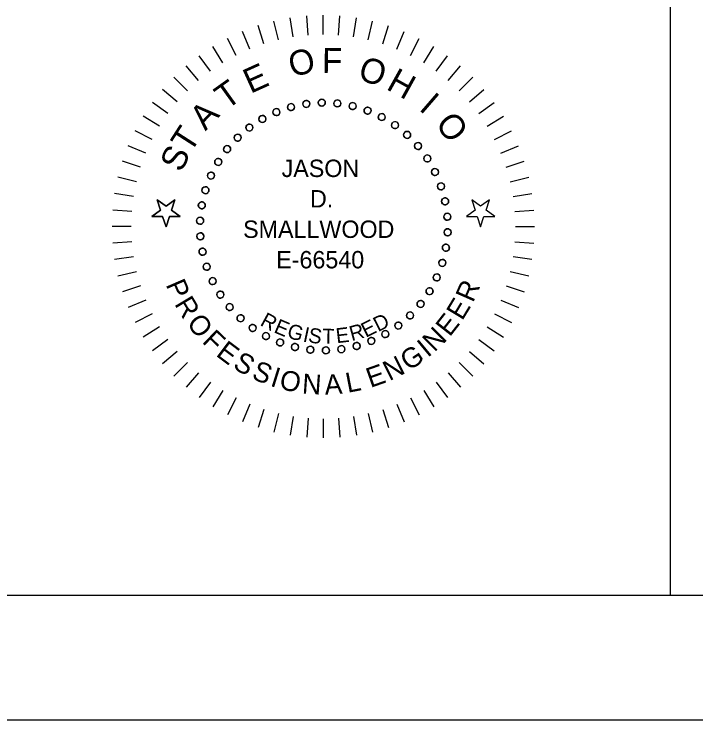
# Model space of a CAD drawing. Extents: x -5.9 to 34, y 0 to 22.
# Drawn here: x 26.559 to 29.302, y 0 to 2.839 of the extents above; entities that cross this region are included whole.
import ezdxf

# ---------------------------------------------------------------- set-up
doc = ezdxf.new("R2010")
doc.units = 0
for name, color, linetype in [('Default', 7, 'Continuous'), ('SH_Border', 7, 'Continuous'), ('SH_Cut_Line', 7, 'Continuous'), ('SH_Data', 7, 'Continuous')]:
    doc.layers.add(name, color=color, linetype=linetype)

msp = doc.modelspace()

# ---------------------------------------------------------------- linework, layer by layer
at = {"layer": 'Default'}
for points in [[(27.6225, 2.7359), (27.6045, 2.8109)], [(27.6821, 2.7478), (27.67, 2.8239)], [(27.7423, 2.7549), (27.7363, 2.8317)], [(27.803, 2.7573), (27.803, 2.8343)], [(27.8636, 2.7549), (27.8697, 2.8317)], [(27.9239, 2.7478), (27.936, 2.8239)], [(27.9834, 2.7359), (28.0014, 2.8109)], [(27.5641, 2.7195), (27.5403, 2.7927)], [(28.0418, 2.7195), (28.0657, 2.7927)], [(27.5072, 2.6984), (27.4777, 2.7696)], [(28.0988, 2.6984), (28.1283, 2.7696)], [(27.4521, 2.673), (27.4171, 2.7417)], [(28.1539, 2.673), (28.1889, 2.7417)], [(27.3991, 2.6434), (27.3588, 2.7091)], [(28.2069, 2.6434), (28.2471, 2.7091)], [(27.3487, 2.6097), (27.3034, 2.672)], [(28.2573, 2.6097), (28.3026, 2.672)], [(27.301, 2.5721), (27.2509, 2.6307)], [(28.305, 2.5721), (28.355, 2.6307)], [(27.2564, 2.5309), (27.2019, 2.5854)], [(28.3495, 2.5309), (28.404, 2.5854)], [(27.2152, 2.4863), (27.1566, 2.5364)], [(28.3907, 2.4863), (28.4493, 2.5364)], [(27.1776, 2.4387), (27.1153, 2.484)], [(28.4283, 2.4387), (28.4907, 2.484)], [(27.1439, 2.3882), (27.0782, 2.4285)], [(28.462, 2.3882), (28.5277, 2.4285)], [(27.1143, 2.3352), (27.0456, 2.3702)], [(28.4917, 2.3352), (28.5604, 2.3702)], [(27.0889, 2.2801), (27.0177, 2.3096)], [(28.5171, 2.2801), (28.5883, 2.3096)], [(27.0679, 2.2232), (26.9946, 2.247)], [(28.5381, 2.2232), (28.6114, 2.247)], [(27.0514, 2.1648), (26.9764, 2.1828)], [(28.5546, 2.1648), (28.6295, 2.1828)], [(27.0395, 2.1052), (26.9634, 2.1173)], [(28.5664, 2.1052), (28.6425, 2.1173)], [(27.1484, 2.0511), (27.1131, 2.0254), (27.1567, 2.0254), (27.1702, 1.984), (27.1837, 2.0254), (27.2273, 2.0254), (27.192, 2.0511), (27.2055, 2.0925), (27.1702, 2.0669), (27.1349, 2.0925), (27.1484, 2.0511)], [(28.471, 2.0925), (28.4358, 2.0669), (28.4005, 2.0925), (28.414, 2.0511), (28.3787, 2.0254), (28.4223, 2.0254), (28.4358, 1.984), (28.4492, 2.0254), (28.4928, 2.0254), (28.4576, 2.0511), (28.471, 2.0925)], [(27.0324, 2.045), (26.9556, 2.051)], [(28.5736, 2.045), (28.6504, 2.051)], [(27.03, 1.9843), (26.953, 1.9843)], [(28.5759, 1.9843), (28.653, 1.9843)], [(27.0324, 1.9237), (26.9556, 1.9176)], [(28.5736, 1.9237), (28.6504, 1.9176)], [(27.0395, 1.8634), (26.9634, 1.8514)], [(28.6425, 1.8514), (28.5664, 1.8634)], [(26.9764, 1.7859), (27.0514, 1.8039)], [(28.5546, 1.8039), (28.6295, 1.7859)], [(27.0679, 1.7455), (26.9946, 1.7217)], [(28.5381, 1.7455), (28.6114, 1.7217)], [(27.0889, 1.6885), (27.0177, 1.659)], [(28.5171, 1.6885), (28.5883, 1.659)], [(27.1143, 1.6334), (27.0456, 1.5984)], [(28.4917, 1.6334), (28.5604, 1.5984)], [(27.1439, 1.5805), (27.0782, 1.5402)], [(28.462, 1.5805), (28.5277, 1.5402)], [(27.1776, 1.53), (27.1153, 1.4847)], [(28.4283, 1.53), (28.4907, 1.4847)], [(27.2152, 1.4823), (27.1566, 1.4323)], [(28.3907, 1.4823), (28.4493, 1.4323)], [(27.2564, 1.4378), (27.2019, 1.3833)], [(28.3495, 1.4378), (28.404, 1.3833)], [(27.301, 1.3966), (27.2509, 1.338)], [(28.305, 1.3966), (28.355, 1.338)], [(27.3487, 1.359), (27.3034, 1.2966)], [(28.2573, 1.359), (28.3026, 1.2966)], [(27.3991, 1.3253), (27.3588, 1.2596)], [(28.2069, 1.3253), (28.2471, 1.2596)], [(27.4521, 1.2956), (27.4171, 1.227)], [(28.1539, 1.2956), (28.1889, 1.227)], [(27.5072, 1.2702), (27.4777, 1.199)], [(28.0988, 1.2702), (28.1283, 1.199)], [(27.5641, 1.2492), (27.5403, 1.1759)], [(27.6225, 1.2327), (27.6045, 1.1578)], [(27.6821, 1.2209), (27.67, 1.1448)], [(27.9239, 1.2209), (27.936, 1.1448)], [(27.9834, 1.2327), (28.0014, 1.1578)], [(28.0418, 1.2492), (28.0657, 1.1759)], [(27.7423, 1.2138), (27.7363, 1.1369)], [(27.803, 1.2114), (27.803, 1.1343)], [(27.8636, 1.2138), (27.8697, 1.1369)]]:
    msp.add_lwpolyline(points, dxfattribs=at)
for points in [[(27.1349, 2.0925), (27.1702, 2.0669), (27.2055, 2.0925), (27.192, 2.0511), (27.2273, 2.0254), (27.1837, 2.0254), (27.1702, 1.984), (27.1567, 2.0254), (27.1131, 2.0254), (27.1484, 2.0511)], [(28.471, 2.0925), (28.4358, 2.0669), (28.4005, 2.0925), (28.414, 2.0511), (28.3787, 2.0254), (28.4223, 2.0254), (28.4358, 1.984), (28.4492, 2.0254), (28.4928, 2.0254), (28.4576, 2.0511)]]:
    msp.add_lwpolyline(points, close=True, dxfattribs=at)
for centre in [(27.6734, 2.4652), (27.7347, 2.4779), (27.797, 2.4829), (27.8596, 2.48), (27.9212, 2.4692), (27.6142, 2.4449), (27.981, 2.4509), (27.558, 2.4173), (28.0381, 2.4251), (27.5057, 2.3829), (28.0915, 2.3925), (28.1403, 2.3534), (27.4582, 2.3423), (27.4161, 2.296), (28.1839, 2.3085), (28.2215, 2.2584), (27.3801, 2.2447), (28.2525, 2.2041), (27.3509, 2.1894), (28.2765, 2.1463), (27.3288, 2.1309), (27.3142, 2.07), (28.2931, 2.0859), (27.3074, 2.0078), (28.3019, 2.024), (27.3084, 1.9452), (28.3029, 1.9614), (28.2961, 1.8992), (27.3172, 1.8833), (28.2815, 1.8383), (27.3338, 1.8229), (28.2594, 1.7798), (27.3578, 1.7651), (28.2302, 1.7245), (27.3888, 1.7108), (28.1942, 1.6732), (27.4264, 1.6607), (27.47, 1.6158), (28.1521, 1.6269), (27.5188, 1.5767), (28.1046, 1.5863), (28.0523, 1.5519), (27.5722, 1.5441), (27.9961, 1.5243), (27.6293, 1.5183), (27.6891, 1.5), (27.8756, 1.4913), (27.9369, 1.504), (27.7507, 1.4892), (27.8133, 1.4863)]:
    msp.add_circle(centre, 0.0141, dxfattribs=at)
for centre, radius, start, end in [((27.6734, 2.4652), 0.0141, 14.4, 194.4), ((27.7347, 2.4779), 0.0141, 7.2, 187.2), ((27.7347, 2.4779), 0.0141, 187.2, 270.9371), ((27.7347, 2.4779), 0.0141, 285.3271, 7.2), ((27.797, 2.4829), 0.0141, 0, 180), ((27.797, 2.4829), 0.0141, 180, 263.7371), ((27.797, 2.4829), 0.0141, 278.1271, 360), ((27.8596, 2.48), 0.0141, 172.8, 256.5371), ((27.8596, 2.48), 0.0141, 352.8, 172.8), ((27.8596, 2.48), 0.0141, 270.9271, 352.8), ((27.9212, 2.4692), 0.0141, 165.6, 249.3371), ((27.9212, 2.4692), 0.0141, 345.6, 165.6), ((27.6142, 2.4449), 0.0141, 21.6, 201.6), ((27.6142, 2.4449), 0.0141, 299.7271, 21.6), ((27.6734, 2.4652), 0.0141, 194.4, 278.1371), ((27.8052, 1.9846), 0.4843, 105.1226, 105.5416), ((27.6734, 2.4652), 0.0141, 292.5271, 14.4), ((27.8052, 1.9846), 0.4843, 97.9226, 98.3416), ((27.8052, 1.9846), 0.4843, 90.7226, 91.1416), ((27.8052, 1.9846), 0.4843, 83.5226, 83.9416), ((27.8052, 1.9846), 0.4843, 76.3226, 76.7416), ((27.9212, 2.4692), 0.0141, 263.7271, 345.6), ((27.981, 2.4509), 0.0141, 158.4, 242.1371), ((27.981, 2.4509), 0.0141, 338.4, 158.4), ((27.981, 2.4509), 0.0141, 256.5271, 338.4), ((27.558, 2.4173), 0.0141, 28.8, 208.8), ((27.558, 2.4173), 0.0141, 306.9271, 28.8), ((27.6142, 2.4449), 0.0141, 201.6, 285.3371), ((27.8052, 1.9846), 0.4843, 112.3226, 112.7416), ((27.8052, 1.9846), 0.4843, 69.1226, 69.5416), ((28.0381, 2.4251), 0.0141, 151.2, 234.9371), ((28.0381, 2.4251), 0.0141, 331.2, 151.2), ((27.8052, 1.9846), 0.4843, 61.9226, 62.3416), ((28.0381, 2.4251), 0.0141, 249.3271, 331.2), ((27.5057, 2.3829), 0.0141, 36, 216), ((27.5057, 2.3829), 0.0141, 314.1271, 36), ((27.558, 2.4173), 0.0141, 208.8, 292.5371), ((27.8052, 1.9846), 0.4843, 119.5226, 119.9416), ((28.0915, 2.3925), 0.0141, 144, 227.7371), ((28.0915, 2.3925), 0.0141, 324, 144), ((27.5057, 2.3829), 0.0141, 216, 299.7371), ((27.8052, 1.9846), 0.4843, 126.7226, 127.1416), ((27.8052, 1.9846), 0.4843, 54.7226, 55.1416), ((28.0915, 2.3925), 0.0141, 242.1271, 324), ((28.1403, 2.3534), 0.0141, 136.8, 220.5371), ((28.1403, 2.3534), 0.0141, 316.8, 136.8), ((27.4582, 2.3423), 0.0141, 43.2, 223.2), ((27.4582, 2.3423), 0.0141, 223.2, 306.9371), ((27.8052, 1.9846), 0.4843, 133.9226, 134.3416), ((27.4582, 2.3423), 0.0141, 321.3271, 43.2), ((27.8052, 1.9846), 0.4843, 47.5226, 47.9416), ((28.1403, 2.3534), 0.0141, 234.9271, 316.8), ((27.4161, 2.296), 0.0141, 50.4, 230.4), ((27.4161, 2.296), 0.0141, 328.5271, 50.4), ((28.1839, 2.3085), 0.0141, 129.6, 213.3371), ((27.8052, 1.9846), 0.4843, 40.3226, 40.7416), ((28.1839, 2.3085), 0.0141, 309.6, 129.6), ((27.4161, 2.296), 0.0141, 230.4, 314.1371), ((27.8052, 1.9846), 0.4843, 141.1226, 141.5416), ((28.1839, 2.3085), 0.0141, 227.7271, 309.6), ((28.2215, 2.2584), 0.0141, 302.4, 122.4), ((27.3801, 2.2447), 0.0141, 57.6, 237.6), ((27.3801, 2.2447), 0.0141, 335.7271, 57.6), ((28.2215, 2.2584), 0.0141, 122.4, 206.1371), ((27.8052, 1.9846), 0.4843, 33.1226, 33.5416), ((28.2215, 2.2584), 0.0141, 220.5271, 302.4), ((27.3801, 2.2447), 0.0141, 237.6, 321.3371), ((27.8052, 1.9846), 0.4843, 148.3226, 148.7416), ((28.2525, 2.2041), 0.0141, 115.2, 198.9371), ((28.2525, 2.2041), 0.0141, 295.2, 115.2), ((27.3509, 2.1894), 0.0141, 64.8, 244.8), ((27.3509, 2.1894), 0.0141, 342.9271, 64.8), ((27.8052, 1.9846), 0.4843, 25.9226, 26.3416), ((28.2525, 2.2041), 0.0141, 213.3271, 295.2), ((27.3509, 2.1894), 0.0141, 244.8, 328.5371), ((27.8052, 1.9846), 0.4843, 155.5226, 155.9416), ((28.2765, 2.1463), 0.0141, 108, 191.7371), ((28.2765, 2.1463), 0.0141, 288, 108), ((27.3288, 2.1309), 0.0141, 72, 252), ((27.3288, 2.1309), 0.0141, 350.1271, 72), ((27.8052, 1.9846), 0.4843, 18.7226, 19.1416), ((28.2765, 2.1463), 0.0141, 206.1271, 288), ((27.3288, 2.1309), 0.0141, 252, 335.7371), ((27.8052, 1.9846), 0.4843, 162.7226, 163.1416), ((27.3142, 2.07), 0.0141, 79.2, 259.2), ((27.3142, 2.07), 0.0141, 357.3271, 79.2), ((28.2931, 2.0859), 0.0141, 100.8, 184.5371), ((27.8052, 1.9846), 0.4843, 11.5226, 11.9416), ((28.2931, 2.0859), 0.0141, 198.9271, 280.8), ((28.2931, 2.0859), 0.0141, 280.8, 100.8), ((27.3142, 2.07), 0.0141, 259.2, 342.9371), ((27.8052, 1.9846), 0.4843, 169.9226, 170.3416), ((27.3074, 2.0078), 0.0141, 86.4, 266.4), ((27.3074, 2.0078), 0.0141, 4.5271, 86.4), ((28.3019, 2.024), 0.0141, 93.6, 177.3371), ((27.8052, 1.9846), 0.4843, 4.3226, 4.7416), ((28.3019, 2.024), 0.0141, 191.7271, 273.6), ((28.3019, 2.024), 0.0141, 273.6, 93.6), ((27.3074, 2.0078), 0.0141, 266.4, 350.1371), ((27.8052, 1.9846), 0.4843, 177.1226, 177.5416), ((27.3084, 1.9452), 0.0141, 93.6, 273.6), ((27.3084, 1.9452), 0.0141, 11.7271, 93.6), ((27.8052, 1.9846), 0.4843, 357.1226, 357.5416), ((28.3029, 1.9614), 0.0141, 184.5271, 266.4), ((28.3029, 1.9614), 0.0141, 86.4, 170.1371), ((28.3029, 1.9614), 0.0141, 266.4, 86.4), ((27.3084, 1.9452), 0.0141, 273.6, 357.3371), ((27.8052, 1.9846), 0.4843, 184.3226, 184.7416), ((27.8052, 1.9846), 0.4843, 349.9226, 350.3416), ((28.2961, 1.8992), 0.0141, 79.2, 162.9371), ((28.2961, 1.8992), 0.0141, 259.2, 79.2), ((27.3172, 1.8833), 0.0141, 100.8, 280.8), ((27.3172, 1.8833), 0.0141, 18.9271, 100.8), ((27.3172, 1.8833), 0.0141, 280.8, 4.5371), ((27.8052, 1.9846), 0.4843, 191.5226, 191.9416), ((28.2961, 1.8992), 0.0141, 177.3271, 259.2), ((28.2815, 1.8383), 0.0141, 72, 155.7371), ((28.2815, 1.8383), 0.0141, 252, 72), ((27.3338, 1.8229), 0.0141, 108, 288), ((27.3338, 1.8229), 0.0141, 26.1271, 108), ((27.3338, 1.8229), 0.0141, 288, 11.7371), ((27.8052, 1.9846), 0.4843, 198.7226, 199.1416), ((28.2815, 1.8383), 0.0141, 170.1271, 252), ((27.8052, 1.9846), 0.4843, 342.7226, 343.1416), ((28.2594, 1.7798), 0.0141, 64.8, 148.5371), ((28.2594, 1.7798), 0.0141, 244.8, 64.8), ((27.3578, 1.7651), 0.0141, 115.2, 295.2), ((27.3578, 1.7651), 0.0141, 33.3271, 115.2), ((27.3578, 1.7651), 0.0141, 295.2, 18.9371), ((27.8052, 1.9846), 0.4843, 205.9226, 206.3416), ((28.2594, 1.7798), 0.0141, 162.9271, 244.8), ((27.8052, 1.9846), 0.4843, 335.5226, 335.9416), ((27.8052, 1.9846), 0.4843, 328.3226, 328.7416), ((28.2302, 1.7245), 0.0141, 57.6, 141.3371), ((28.2302, 1.7245), 0.0141, 237.6, 57.6), ((27.3888, 1.7108), 0.0141, 122.4, 302.4), ((27.3888, 1.7108), 0.0141, 40.5271, 122.4), ((27.3888, 1.7108), 0.0141, 302.4, 26.1371), ((27.8052, 1.9846), 0.4843, 213.1226, 213.5416), ((28.2302, 1.7245), 0.0141, 155.7271, 237.6), ((28.1942, 1.6732), 0.0141, 148.5271, 230.4), ((27.8052, 1.9846), 0.4843, 321.1226, 321.5416), ((28.1942, 1.6732), 0.0141, 50.4, 134.1371), ((28.1942, 1.6732), 0.0141, 230.4, 50.4), ((27.4264, 1.6607), 0.0141, 129.6, 309.6), ((27.4264, 1.6607), 0.0141, 47.7271, 129.6), ((27.4264, 1.6607), 0.0141, 309.6, 33.3371), ((27.8052, 1.9846), 0.4843, 220.3226, 220.7416), ((27.47, 1.6158), 0.0141, 136.8, 316.8), ((27.47, 1.6158), 0.0141, 54.9271, 136.8), ((27.8052, 1.9846), 0.4843, 227.5226, 227.9416), ((27.47, 1.6158), 0.0141, 316.8, 40.5371), ((28.1521, 1.6269), 0.0141, 141.3271, 223.2), ((27.8052, 1.9846), 0.4843, 313.9226, 314.3416), ((28.1521, 1.6269), 0.0141, 223.2, 43.2), ((28.1521, 1.6269), 0.0141, 43.2, 126.9371), ((27.5188, 1.5767), 0.0141, 62.1271, 144), ((28.1046, 1.5863), 0.0141, 134.1271, 216), ((28.1046, 1.5863), 0.0141, 216, 36), ((27.8052, 1.9846), 0.4843, 306.7226, 307.1416), ((28.1046, 1.5863), 0.0141, 36, 119.7371), ((27.5188, 1.5767), 0.0141, 144, 324), ((27.8052, 1.9846), 0.4843, 234.7226, 235.1416), ((27.5188, 1.5767), 0.0141, 324, 47.7371), ((28.0523, 1.5519), 0.0141, 126.9271, 208.8), ((27.8052, 1.9846), 0.4843, 299.5226, 299.9416), ((28.0523, 1.5519), 0.0141, 28.8, 112.5371), ((27.5722, 1.5441), 0.0141, 151.2, 331.2), ((27.5722, 1.5441), 0.0141, 69.3271, 151.2), ((27.8052, 1.9846), 0.4843, 241.9226, 242.3416), ((27.5722, 1.5441), 0.0141, 331.2, 54.9371), ((27.9961, 1.5243), 0.0141, 119.7271, 201.6), ((27.8052, 1.9846), 0.4843, 292.3226, 292.7416), ((27.9961, 1.5243), 0.0141, 21.6, 105.3371), ((28.0523, 1.5519), 0.0141, 208.8, 28.8), ((27.6293, 1.5183), 0.0141, 158.4, 338.4), ((27.6293, 1.5183), 0.0141, 76.5271, 158.4), ((27.8052, 1.9846), 0.4843, 249.1226, 249.5416), ((27.6293, 1.5183), 0.0141, 338.4, 62.1371), ((27.6891, 1.5), 0.0141, 83.7271, 165.6), ((27.8052, 1.9846), 0.4843, 256.3226, 256.7416), ((27.6891, 1.5), 0.0141, 345.6, 69.3371), ((27.8756, 1.4913), 0.0141, 105.3271, 187.2), ((27.8052, 1.9846), 0.4843, 277.9226, 278.3416), ((27.8756, 1.4913), 0.0141, 7.2, 90.9371), ((27.9369, 1.504), 0.0141, 112.5271, 194.4), ((27.9369, 1.504), 0.0141, 194.4, 14.4), ((27.8052, 1.9846), 0.4843, 285.1226, 285.5416), ((27.9369, 1.504), 0.0141, 14.4, 98.1371), ((27.9961, 1.5243), 0.0141, 201.6, 21.6), ((27.6891, 1.5), 0.0141, 165.6, 345.6), ((27.7507, 1.4892), 0.0141, 172.8, 352.8), ((27.7507, 1.4892), 0.0141, 90.9271, 172.8), ((27.8052, 1.9846), 0.4843, 263.5226, 263.9416), ((27.7507, 1.4892), 0.0141, 352.8, 76.5371), ((27.8133, 1.4863), 0.0141, 98.1271, 180), ((27.8133, 1.4863), 0.0141, 180, 0), ((27.8052, 1.9846), 0.4843, 270.7226, 271.1416), ((27.8133, 1.4863), 0.0141, 360, 83.7371), ((27.8756, 1.4913), 0.0141, 187.2, 7.2)]:
    msp.add_arc(centre, radius, start, end, dxfattribs=at)
at = {"layer": 'SH_Border'}
msp.add_lwpolyline([(1.5, 21.5), (33.5, 21.5), (33.5, 0.5), (1.5, 0.5)], close=True, dxfattribs=at)
at = {"layer": 'SH_Cut_Line'}
msp.add_lwpolyline([(0, 0), (34, 0), (34, 22), (0, 22)], close=True, dxfattribs=at)
at = {"layer": 'SH_Data'}
msp.add_line((29.2, 0.5), (29.2, 3.75), dxfattribs=at)

# ---------------------------------------------------------------- texts
at = {"layer": 'Default'}
for s, height, rotation, p in [('O', 0.1, 13.3854, (27.6763, 2.5854)), ('F', 0.1, 359.678, (27.7977, 2.6027)), ('E', 0.1, 24.2623, (27.51, 2.5179)), ('O', 0.1, 342.0191, (27.9377, 2.5778)), ('H', 0.1, 330.9889, (28.0523, 2.539)), ('T', 0.1, 35.6514, (27.4134, 2.452)), ('I', 0.1, 319.1518, (28.1844, 2.4555)), ('A', 0.1, 46.5856, (27.3289, 2.367)), ('O', 0.1, 307.5099, (28.2505, 2.3964)), ('T', 0.1, 57.2766, (27.2681, 2.2759)), ('S', 0.1, 64.8956, (27.2324, 2.199)), ('P', 0.08, 293.3065, (27.168, 1.7513)), ('R', 0.08, 66.294, (28.4051, 1.6758)), ('R', 0.08, 300.7913, (27.2022, 1.6733)), ('E', 0.08, 58.867, (28.3618, 1.6032)), ('O', 0.08, 308.9294, (27.2503, 1.5938)), ('R', 0.06, 331.5179, (27.5453, 1.5893)), ('D', 0.06, 26.8755, (28.0234, 1.5595)), ('E', 0.08, 51.8972, (28.3114, 1.5382)), ('E', 0.06, 337.0101, (27.6006, 1.5601)), ('G', 0.06, 344.9102, (27.6538, 1.5381)), ('R', 0.06, 15.2924, (27.9171, 1.5233)), ('E', 0.06, 26.5869, (27.974, 1.5366)), ('F', 0.08, 316.3676, (27.3123, 1.5191)), ('I', 0.06, 347.8825, (27.7181, 1.5226)), ('S', 0.06, 351.4682, (27.7398, 1.5193)), ('T', 0.06, 359.0333, (27.7984, 1.5137)), ('E', 0.06, 6.5708, (27.8568, 1.5151)), ('N', 0.08, 44.7866, (28.2501, 1.4766)), ('E', 0.08, 323.0948, (27.3676, 1.4667)), ('I', 0.08, 39.7574, (28.223, 1.4552)), ('G', 0.08, 34.2643, (28.1473, 1.4017)), ('S', 0.08, 330.2332, (27.4353, 1.4166)), ('N', 0.08, 26.5487, (28.0687, 1.3621)), ('S', 0.08, 337.5402, (27.5105, 1.3744)), ('E', 0.08, 19.438, (27.9926, 1.335)), ('I', 0.08, 342.597, (27.5862, 1.3445)), ('O', 0.08, 348.1963, (27.6223, 1.3321)), ('N', 0.08, 356.0181, (27.7158, 1.3134)), ('L', 0.08, 10.971, (27.901, 1.3154)), ('A', 0.08, 3.7707, (27.8102, 1.308))]:
    msp.add_text(s, height=height, rotation=rotation, dxfattribs=at).set_placement(p)
for s, p in [('JASON', (27.6353, 2.1838)), ('D.', (27.7494, 2.0613)), ('SMALLWOOD', (27.4804, 1.9388)), ('E-66540', (27.6135, 1.8163))]:
    msp.add_text(s, height=0.07, dxfattribs=at).set_placement(p)

doc.saveas('drawing.dxf')
